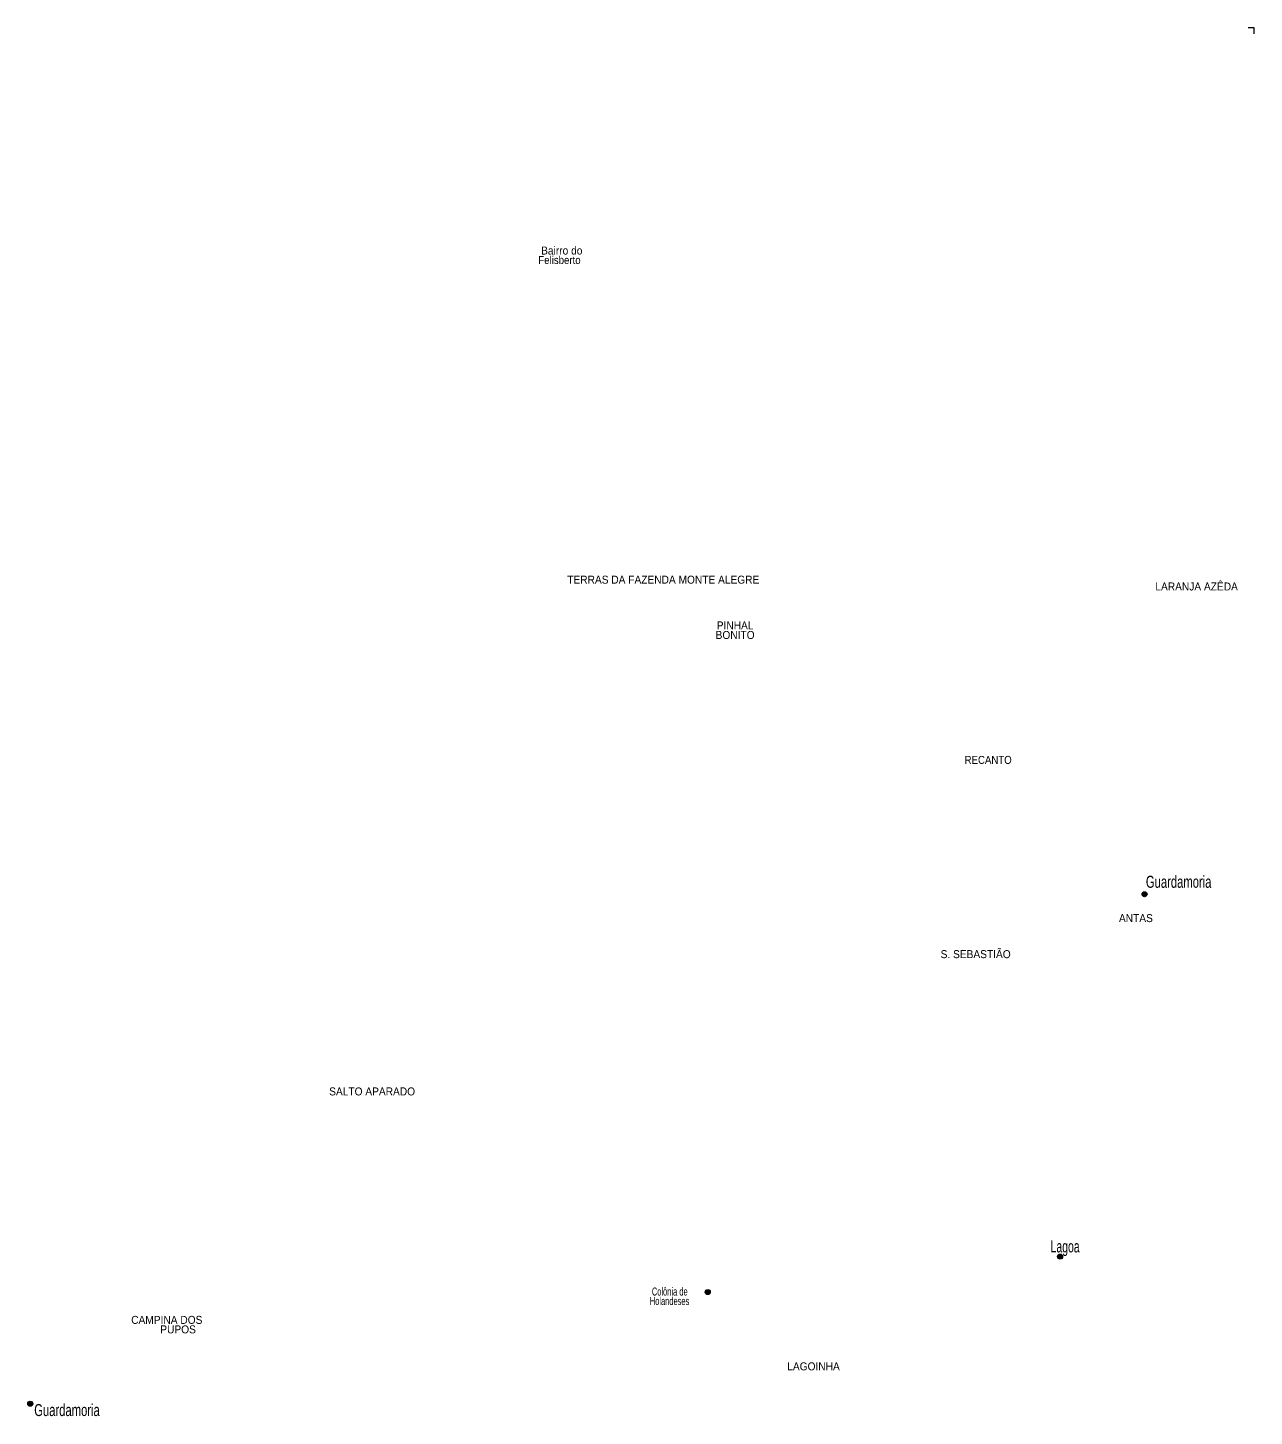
# Model space of a CAD drawing. Extents: x 500 to 550.9, y 7290.3 to 7345.7.
# Drawn here: x 526.34 to 550.86, y 7317.9 to 7345.66 of the extents above; entities that cross this region are included whole.
import ezdxf
from ezdxf.enums import TextEntityAlignment as Align

# ---------------------------------------------------------------- set-up
doc = ezdxf.new("R2010")
doc.units = 0
doc.header["$LTSCALE"] = 0.064
doc.layers.add('52', color=7, linetype='Continuous', lineweight=13)
doc.layers.add('63', color=7, linetype='Continuous', lineweight=13)
doc.layers.add('56', color=7, linetype='Continuous')
doc.layers.add('61', color=7, linetype='Continuous')

msp = doc.modelspace()

# ---------------------------------------------------------------- hatches: boundary and pattern name
at = {"layer": '52'}
for points in [[(548.71539, 7328.33856, 1), (548.61539, 7328.33856, 1)], [(547.02729, 7321.09406, 1), (546.92729, 7321.09406, 1)], [(539.98319, 7320.38486, 1), (539.88319, 7320.38486, 1)], [(526.43839, 7318.15376, 1), (526.33839, 7318.15376, 1)]]:
    msp.add_hatch(color=256, dxfattribs=at).paths.add_polyline_path(points)

# ---------------------------------------------------------------- linework, layer by layer
for centre in [(548.66539, 7328.33856), (546.97729, 7321.09406), (539.93319, 7320.38486), (526.38839, 7318.15376)]:
    msp.add_circle(centre, 0.05, dxfattribs=at)
at = {"layer": '63'}
msp.add_lwpolyline([(550.8587, 7345.5355), (550.8587, 7345.6587), (550.7373, 7345.6587)], dxfattribs=at)

# ---------------------------------------------------------------- texts
at = {"layer": '56'}
for s, width, p in [('TERRAS DA FAZENDA MONTE ALEGRE', 0.95, (539.04425, 7334.5465)), ('LARANJA AZÊDA', 0.95, (549.7066, 7334.4098)), ('PINHAL', 0.95, (540.4801, 7333.6313)), ('BONITO', 0.95, (540.4801, 7333.4413)), ('RECANTO', 0.9, (545.53915, 7330.943)), ('ANTAS', 0.95, (548.493, 7327.7809)), ('S. SEBASTIÃO', 0.95, (545.2893, 7327.0604)), ('SALTO APARADO', 0.95, (533.22315, 7324.3162)), ('CAMPINA DOS', 0.95, (529.11775, 7319.7495)), ('        PUPOS', 0.95, (529.11765, 7319.5595)), ('LAGOINHA', 0.95, (542.0475, 7318.8204))]:
    msp.add_text(s, height=0.16, dxfattribs=dict(at, width=width)).set_placement(p, align=Align.CENTER)
at = {"layer": '61'}
for s, height, width, p in [(' Bairro do', 0.16, 0.95, (536.5459, 7341.1255)), ('Felisberto', 0.16, 0.9, (536.5459, 7340.9355)), ('Guardamoria', 0.24, 0.7, (548.6925, 7328.4668)), ('Lagoa', 0.24, 0.65, (546.7881, 7321.1778)), (' Colônia de', 0.16, 0.7, (538.7736, 7320.3158)), ('Holandeses', 0.16, 0.7, (538.7736, 7320.1258)), ('Guardamoria', 0.24, 0.7, (526.4677, 7317.9068))]:
    msp.add_text(s, height=height, dxfattribs=dict(at, width=width)).set_placement(p)

doc.saveas('drawing.dxf')
